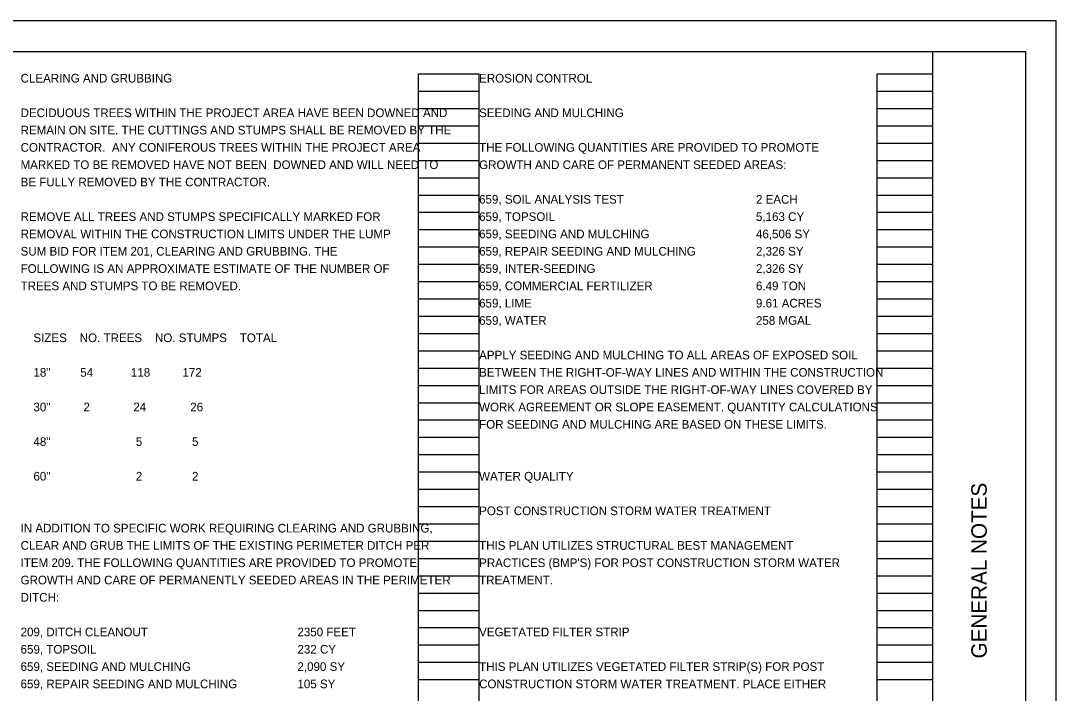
# Model space of a CAD drawing. Extents: x -19 to 64.6, y -1.7 to 22.
# Drawn here: x 17.24 to 34, y 11.12 to 22 of the extents above; entities that cross this region are included whole.
import ezdxf

# ---------------------------------------------------------------- set-up
doc = ezdxf.new("R2010")
doc.units = 0
for name, color, linetype in [('SH_Border', 7, 'Continuous'), ('SH_Cut_Line', 7, 'Continuous'), ('SH_Data', 7, 'Continuous'), ('SH_Text', 7, 'Continuous')]:
    doc.layers.add(name, color=color, linetype=linetype)

msp = doc.modelspace()

# ---------------------------------------------------------------- linework, layer by layer
at = {"layer": 'SH_Border'}
msp.add_line((32, 0.5), (32, 21.5), dxfattribs=at)
msp.add_lwpolyline([(1.5, 21.5), (33.5, 21.5), (33.5, 0.5), (1.5, 0.5)], close=True, dxfattribs=at)
at = {"layer": 'SH_Cut_Line'}
msp.add_lwpolyline([(0, 0), (34, 0), (34, 22), (0, 22)], close=True, dxfattribs=at)
at = {"layer": 'SH_Data'}
for p, q in [((23.68, 0.98), (23.68, 21.14)), ((23.68, 21.14), (24.66, 21.14)), ((24.66, 0.98), (24.66, 21.14)), ((31.1, 0.98), (31.1, 21.14)), ((31.1, 21.14), (32, 21.14)), ((32, 0.98), (32, 21.14)), ((23.68, 20.86), (24.66, 20.86)), ((31.1, 20.86), (32, 20.86)), ((23.68, 20.58), (24.66, 20.58)), ((31.1, 20.58), (32, 20.58)), ((23.68, 20.3), (24.66, 20.3)), ((31.1, 20.3), (32, 20.3)), ((23.68, 20.02), (24.66, 20.02)), ((31.1, 20.02), (32, 20.02)), ((23.68, 19.74), (24.66, 19.74)), ((31.1, 19.74), (32, 19.74)), ((23.68, 19.46), (24.66, 19.46)), ((31.1, 19.46), (32, 19.46)), ((23.68, 19.18), (24.66, 19.18)), ((31.1, 19.18), (32, 19.18)), ((23.68, 18.9), (24.66, 18.9)), ((31.1, 18.9), (32, 18.9)), ((23.68, 18.62), (24.66, 18.62)), ((31.1, 18.62), (32, 18.62)), ((23.68, 18.34), (24.66, 18.34)), ((31.1, 18.34), (32, 18.34)), ((23.68, 18.06), (24.66, 18.06)), ((31.1, 18.06), (32, 18.06)), ((23.68, 17.78), (24.66, 17.78)), ((31.1, 17.78), (32, 17.78)), ((23.68, 17.5), (24.66, 17.5)), ((31.1, 17.5), (32, 17.5)), ((23.68, 17.22), (24.66, 17.22)), ((31.1, 17.22), (32, 17.22)), ((23.68, 16.94), (24.66, 16.94)), ((31.1, 16.94), (32, 16.94)), ((23.68, 16.66), (24.66, 16.66)), ((31.1, 16.66), (32, 16.66)), ((23.68, 16.38), (24.66, 16.38)), ((31.1, 16.38), (32, 16.38)), ((23.68, 16.1), (24.66, 16.1)), ((31.1, 16.1), (32, 16.1)), ((23.68, 15.82), (24.66, 15.82)), ((31.1, 15.82), (32, 15.82)), ((23.68, 15.54), (24.66, 15.54)), ((31.1, 15.54), (32, 15.54)), ((23.68, 15.26), (24.66, 15.26)), ((31.1, 15.26), (32, 15.26)), ((23.68, 14.98), (24.66, 14.98)), ((31.1, 14.98), (32, 14.98)), ((23.68, 14.7), (24.66, 14.7)), ((31.1, 14.7), (32, 14.7)), ((23.68, 14.42), (24.66, 14.42)), ((31.1, 14.42), (32, 14.42)), ((23.68, 14.14), (24.66, 14.14)), ((31.1, 14.14), (32, 14.14)), ((23.68, 13.86), (24.66, 13.86)), ((31.1, 13.86), (32, 13.86)), ((23.68, 13.58), (24.66, 13.58)), ((31.1, 13.58), (32, 13.58)), ((23.68, 13.3), (24.66, 13.3)), ((31.1, 13.3), (32, 13.3)), ((23.68, 13.02), (24.66, 13.02)), ((31.1, 13.02), (32, 13.02)), ((23.68, 12.74), (24.66, 12.74)), ((31.1, 12.74), (32, 12.74)), ((23.68, 12.46), (24.66, 12.46)), ((31.1, 12.46), (32, 12.46)), ((23.68, 12.18), (24.66, 12.18)), ((31.1, 12.18), (32, 12.18)), ((23.68, 11.9), (24.66, 11.9)), ((31.1, 11.9), (32, 11.9)), ((23.68, 11.62), (24.66, 11.62)), ((31.1, 11.62), (32, 11.62)), ((23.68, 11.34), (24.66, 11.34)), ((31.1, 11.34), (32, 11.34))]:
    msp.add_line(p, q, dxfattribs=at)

# ---------------------------------------------------------------- texts
msp.add_text('GENERAL NOTES', height=0.25, rotation=90, dxfattribs=at).set_placement((32.875, 11.682))
at = {"layer": 'SH_Text'}
for s, p in [('CLEARING AND GRUBBING', (17.24, 21)), ('EROSION CONTROL', (24.66, 21)), ('DECIDUOUS TREES WITHIN THE PROJECT AREA HAVE BEEN DOWNED AND ', (17.24, 20.44)), ('SEEDING AND MULCHING', (24.66, 20.44)), ('REMAIN ON SITE. THE CUTTINGS AND STUMPS SHALL BE REMOVED BY THE ', (17.24, 20.16)), ('CONTRACTOR.  ANY CONIFEROUS TREES WITHIN THE PROJECT AREA ', (17.24, 19.88)), ('THE FOLLOWING QUANTITIES ARE PROVIDED TO PROMOTE', (24.66, 19.88)), ('MARKED TO BE REMOVED HAVE NOT BEEN  DOWNED AND WILL NEED TO ', (17.24, 19.6)), ('GROWTH AND CARE OF PERMANENT SEEDED AREAS:', (24.66, 19.6)), ('BE FULLY REMOVED BY THE CONTRACTOR.', (17.24, 19.32)), ('659, SOIL ANALYSIS TEST            ', (24.66, 19.04)), ('2 EACH', (29.14, 19.04)), ('REMOVE ALL TREES AND STUMPS SPECIFICALLY MARKED FOR', (17.24, 18.76)), ('659, TOPSOIL                       ', (24.66, 18.76)), ('5,163 CY', (29.14, 18.76)), ('REMOVAL WITHIN THE CONSTRUCTION LIMITS UNDER THE LUMP', (17.24, 18.48)), ('659, SEEDING AND MULCHING          ', (24.66, 18.48)), ('46,506 SY', (29.14, 18.48)), ('SUM BID FOR ITEM 201, CLEARING AND GRUBBING. THE', (17.24, 18.2)), ('659, REPAIR SEEDING AND MULCHING   ', (24.66, 18.2)), ('2,326 SY', (29.14, 18.2)), ('FOLLOWING IS AN APPROXIMATE ESTIMATE OF THE NUMBER OF', (17.24, 17.92)), ('659, INTER-SEEDING                 ', (24.66, 17.92)), ('2,326 SY', (29.14, 17.92)), ('TREES AND STUMPS TO BE REMOVED.', (17.24, 17.64)), ('659, COMMERCIAL FERTILIZER         ', (24.66, 17.64)), ('6.49 TON', (29.14, 17.64)), ('659, LIME                          ', (24.66, 17.36)), ('9.61 ACRES', (29.14, 17.36)), ('659, WATER                         ', (24.66, 17.08)), ('258 MGAL', (29.14, 17.08)), ('    SIZES    NO. TREES    NO. STUMPS    TOTAL', (17.24, 16.8)), ('APPLY SEEDING AND MULCHING TO ALL AREAS OF EXPOSED SOIL ', (24.66, 16.52)), ('    18"      ', (17.24, 16.24)), ('   54  ', (18.05, 16.24)), ('  118 ', (18.921, 16.24)), ('  172  ', (19.755, 16.24)), ('BETWEEN THE RIGHT-OF-WAY LINES AND WITHIN THE CONSTRUCTION ', (24.66, 16.24)), ('LIMITS FOR AREAS OUTSIDE THE RIGHT-OF-WAY LINES COVERED BY ', (24.66, 15.96)), ('    30"      ', (17.24, 15.68)), ('    2   ', (18.05, 15.68)), ('   24   ', (18.909, 15.68)), ('   26   ', (19.83, 15.68)), ('WORK AGREEMENT OR SLOPE EASEMENT. QUANTITY CALCULATIONS ', (24.66, 15.68)), ('FOR SEEDING AND MULCHING ARE BASED ON THESE LIMITS.', (24.66, 15.4)), ('    48"      ', (17.24, 15.12)), ('    5    ', (18.897, 15.12)), ('    5    ', (19.806, 15.12)), ('    60"      ', (17.24, 14.56)), ('    2    ', (18.897, 14.56)), ('    2    ', (19.806, 14.56)), ('WATER QUALITY', (24.66, 14.56)), ('POST CONSTRUCTION STORM WATER TREATMENT', (24.66, 14)), ('IN ADDITION TO SPECIFIC WORK REQUIRING CLEARING AND GRUBBING, ', (17.24, 13.72)), ('CLEAR AND GRUB THE LIMITS OF THE EXISTING PERIMETER DITCH PER ', (17.24, 13.44)), ('THIS PLAN UTILIZES STRUCTURAL BEST MANAGEMENT', (24.66, 13.44)), ('ITEM 209. THE FOLLOWING QUANTITIES ARE PROVIDED TO PROMOTE ', (17.24, 13.16)), ("PRACTICES (BMP'S) FOR POST CONSTRUCTION STORM WATER", (24.66, 13.16)), ('GROWTH AND CARE OF PERMANENTLY SEEDED AREAS IN THE PERIMETER ', (17.24, 12.88)), ('TREATMENT.', (24.66, 12.88)), ('DITCH:', (17.24, 12.6)), ('209, DITCH CLEANOUT           ', (17.24, 12.04)), ('2350 FEET', (21.72, 12.04)), ('VEGETATED FILTER STRIP', (24.66, 12.04)), ('659, TOPSOIL                       ', (17.24, 11.76)), ('232 CY', (21.72, 11.76)), ('659, SEEDING AND MULCHING          ', (17.24, 11.48)), ('2,090 SY', (21.72, 11.48)), ('THIS PLAN UTILIZES VEGETATED FILTER STRIP(S) FOR POST', (24.66, 11.48)), ('659, REPAIR SEEDING AND MULCHING   ', (17.24, 11.2)), ('105 SY', (21.72, 11.2)), ('CONSTRUCTION STORM WATER TREATMENT. PLACE EITHER', (24.66, 11.2))]:
    msp.add_text(s, height=0.14, dxfattribs=at).set_placement(p)

doc.saveas('drawing.dxf')
